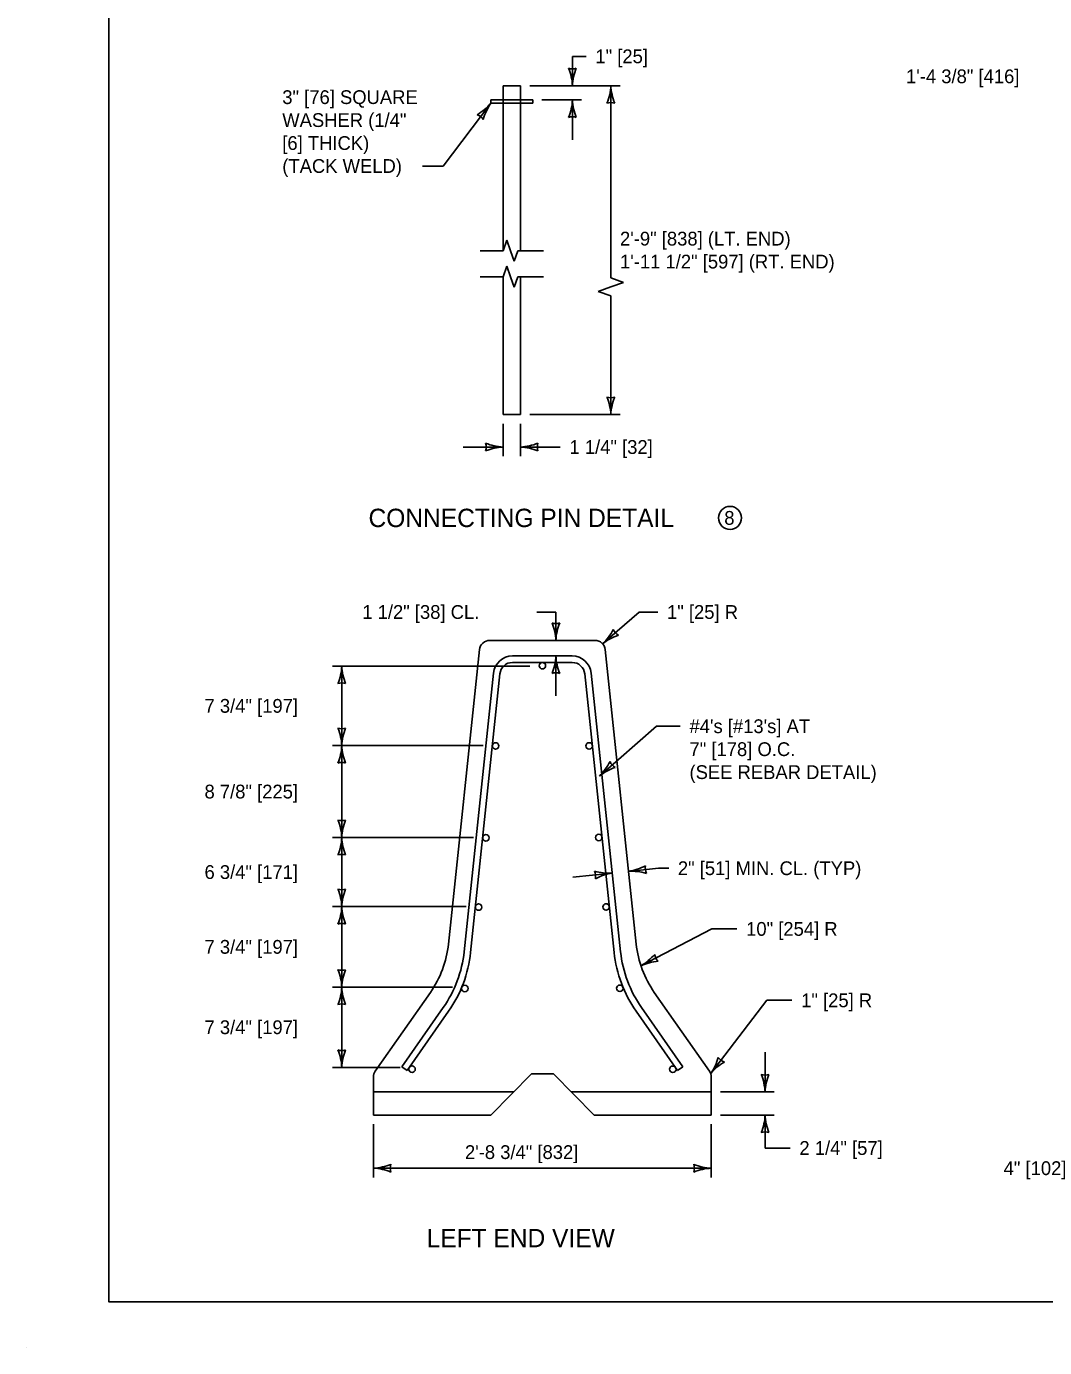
# Model space of a CAD drawing. Extents: x 49991.4 to 50021, y 49987.6 to 50011.4.
# Drawn here: x 49999.02 to 50003.46, y 49987.6 to 49993.36 of the extents above; entities that cross this region are included whole.
import ezdxf

# ---------------------------------------------------------------- set-up
doc = ezdxf.new("R2010")
doc.units = 0
for name, color, linetype in [('Level 1', 7, 'Continuous'), ('Level 2', 7, 'Continuous'), ('Level 3', 7, 'Continuous'), ('Level 4', 7, 'Continuous'), ('Level 6', 7, 'Continuous')]:
    doc.layers.add(name, color=color, linetype=linetype)

msp = doc.modelspace()

# ---------------------------------------------------------------- linework, layer by layer
at = {"layer": 'Level 1'}
for p, q in [((50001.1781, 49993.0967), (50001.1019, 49993.0967)), ((50001.1019, 49993.0967), (50001.1019, 49992.3777)), ((50001.1781, 49992.3774), (50001.1781, 49993.0967)), ((50001.0485, 49993.0358), (50001.2314, 49993.0358)), ((50001.0485, 49993.0205), (50001.0485, 49993.0358)), ((50001.2314, 49993.0205), (50001.0485, 49993.0205)), ((50001.2314, 49993.0358), (50001.2314, 49993.0205)), ((50001.1019, 49992.2643), (50001.1019, 49991.6639)), ((50001.1781, 49992.264), (50001.1781, 49991.6639)), ((50001.1019, 49991.6639), (50001.1781, 49991.6639)), ((50001.5025, 49990.6801), (50001.044, 49990.6801)), ((50000.9993, 49990.6398), (50000.864, 49989.357)), ((50001.6825, 49989.357), (50001.5472, 49990.6398)), ((50001.4033, 49990.6123), (50001.1432, 49990.6123)), ((50001.4033, 49990.5839), (50001.1432, 49990.5839)), ((50001.0604, 49990.5377), (50000.9324, 49989.3236)), ((50001.0886, 49990.5347), (50000.9606, 49989.3206)), ((50001.586, 49989.3206), (50001.458, 49990.5347)), ((50001.6142, 49989.3236), (50001.4862, 49990.5377)), ((50000.7852, 49989.1463), (50000.5452, 49988.8035)), ((50002.0013, 49988.8035), (50001.7613, 49989.1463)), ((50000.8414, 49989.0803), (50000.6604, 49988.8218)), ((50001.8861, 49988.8218), (50001.7052, 49989.0803)), ((50000.8646, 49989.0641), (50000.6837, 49988.8056)), ((50001.8629, 49988.8056), (50001.682, 49989.0641)), ((50000.5371, 49988.7778), (50000.5371, 49988.6121)), ((50000.6837, 49988.8056), (50000.6604, 49988.8218)), ((50001.2262, 49988.7921), (50001.049, 49988.6121)), ((50001.2262, 49988.7921), (50001.3218, 49988.7921)), ((50001.3218, 49988.7921), (50001.499, 49988.6121)), ((50001.8629, 49988.8056), (50001.8861, 49988.8218)), ((50002.0094, 49988.6121), (50002.0094, 49988.7778)), ((50000.5371, 49988.6121), (50001.049, 49988.6121)), ((50001.499, 49988.6121), (50002.0094, 49988.6121)), ((49999.0245, 49987.5988), (49999.0245, 49987.5988))]:
    msp.add_line(p, q, dxfattribs=at)
msp.add_lwpolyline([(49999.3835, 49998.9992), (50016.7501, 49998.9992), (50016.7501, 49987.7988), (49999.3835, 49987.7988)], close=True, dxfattribs=at)
for centre in [(50001.2733, 49990.5698), (50001.0697, 49990.2201), (50001.4769, 49990.2201), (50001.0274, 49989.8195), (50001.519, 49989.8211), (50000.9956, 49989.5181), (50001.5509, 49989.5185), (50000.935, 49989.1632), (50001.6112, 49989.1641), (50000.7052, 49988.8116), (50001.8416, 49988.8113)]:
    msp.add_circle(centre, 0.0142, dxfattribs=at)
for centre, radius, start, end in [((50001.044, 49990.6351), 0.045, 90, 173.97934), ((50001.5025, 49990.6351), 0.045, 6.02066, 90), ((50001.1432, 49990.529), 0.0833, 90, 173.97934), ((50001.1432, 49990.529), 0.0549, 90, 173.97934), ((50001.4033, 49990.529), 0.0833, 6.02066, 90), ((50001.4033, 49990.529), 0.0549, 6.02066, 90), ((50000.4169, 49989.4041), 0.4496, 325.00798, 353.97934), ((50002.1296, 49989.4041), 0.4496, 186.02066, 214.99202), ((50000.4161, 49989.378), 0.5191, 325.00798, 353.97934), ((50000.4161, 49989.378), 0.5475, 325.00798, 353.97934), ((50002.1305, 49989.378), 0.5475, 186.02066, 214.99202), ((50002.1305, 49989.378), 0.5191, 186.02066, 214.99202), ((50000.5821, 49988.7778), 0.045, 145.00798, 180), ((50001.9645, 49988.7778), 0.045, 0, 34.99202)]:
    msp.add_arc(centre, radius, start, end, dxfattribs=at)
at = {"layer": 'Level 2'}
msp.add_circle((50002.0912, 49991.2137), 0.05, dxfattribs=at)
at = {"layer": 'Level 3'}
for p, q in [((50001.4044, 49993.2247), (50001.4044, 49993.0968)), ((50001.4044, 49993.2247), (50001.4644, 49993.2247)), ((50001.2181, 49993.0968), (50001.6117, 49993.0968)), ((50001.5717, 49993.0968), (50001.5717, 49992.259)), ((50001.0485, 49993.0205), (50000.8406, 49992.7469)), ((50001.2714, 49993.0348), (50001.4443, 49993.0348)), ((50001.4043, 49993.0348), (50001.4043, 49992.8614)), ((50000.7509, 49992.7469), (50000.8406, 49992.7469)), ((50001.6263, 49992.2396), (50001.5717, 49992.259)), ((50001.6263, 49992.2396), (50001.5717, 49992.2202)), ((50001.5717, 49992.2202), (50001.5167, 49992.2007)), ((50001.5717, 49992.1813), (50001.5167, 49992.2007)), ((50001.5717, 49992.1813), (50001.5717, 49991.664)), ((50001.2181, 49991.664), (50001.6117, 49991.664)), ((50001.1018, 49991.6239), (50001.1018, 49991.4825)), ((50001.178, 49991.6239), (50001.178, 49991.4825)), ((50001.1018, 49991.5225), (50000.9284, 49991.5225)), ((50001.178, 49991.5225), (50001.3515, 49991.5225)), ((50001.2486, 49990.8036), (50001.3321, 49990.8036)), ((50001.3321, 49990.6801), (50001.3321, 49990.8036)), ((50001.5359, 49990.6653), (50001.6959, 49990.8036)), ((50001.6959, 49990.8036), (50001.7766, 49990.8036)), ((50001.2192, 49990.568), (50000.3591, 49990.568)), ((50000.3991, 49990.2215), (50000.3991, 49990.568)), ((50001.3321, 49990.6123), (50001.3321, 49990.4388)), ((50001.5219, 49990.0889), (50001.7704, 49990.306)), ((50001.7704, 49990.306), (50001.8746, 49990.306)), ((50001.0156, 49990.2215), (50000.3591, 49990.2215)), ((50000.3991, 49989.8212), (50000.3991, 49990.2215)), ((50000.9733, 49989.8212), (50000.3591, 49989.8212)), ((50000.3991, 49989.5201), (50000.3991, 49989.8212)), ((50001.4056, 49989.6479), (50001.5781, 49989.6661)), ((50001.6491, 49989.6736), (50001.7788, 49989.6873)), ((50001.7788, 49989.6873), (50001.8238, 49989.6873)), ((50000.9416, 49989.5201), (50000.3591, 49989.5201)), ((50000.3991, 49989.1693), (50000.3991, 49989.5201)), ((50001.7031, 49989.2621), (50002.0117, 49989.4229)), ((50002.0117, 49989.4229), (50002.1214, 49989.4229)), ((50000.8822, 49989.1693), (50000.3591, 49989.1693)), ((50000.3991, 49988.8196), (50000.3991, 49989.1693)), ((50002.0069, 49988.7927), (50002.2516, 49989.1118)), ((50002.2516, 49989.1118), (50002.3613, 49989.1118)), ((50002.244, 49988.7129), (50002.244, 49988.8863)), ((50000.6535, 49988.8196), (50000.3591, 49988.8196)), ((50002.0494, 49988.7129), (50002.284, 49988.7129)), ((50002.0494, 49988.6121), (50002.284, 49988.6121)), ((50002.244, 49988.4683), (50002.244, 49988.6121)), ((50000.5371, 49988.5721), (50000.5371, 49988.3404)), ((50002.0094, 49988.5721), (50002.0094, 49988.3404)), ((50002.244, 49988.4683), (50002.3537, 49988.4683)), ((50000.5371, 49988.3804), (50002.0094, 49988.3804))]:
    msp.add_line(p, q, dxfattribs=at)
for centre, radius, start, end in [((50001.4044, 49993.225), 0.0548, 252.13882, 287.86118), ((50001.1717, 49993.0853), 0.233, 2.82731, 22.07716), ((50001.6265, 49993.0877), 0.2223, 157.45601, 177.63952), ((50001.3496, 49993.106), 0.2223, 337.45601, 357.63952), ((50001.8044, 49993.1083), 0.233, 182.82731, 202.07716), ((50000.8771, 49993.1622), 0.2223, 300.23782, 320.42133), ((50001.2408, 49992.8889), 0.233, 145.60912, 164.85897), ((50001.1822, 49993.044), 0.2223, 337.45601, 357.63952), ((50001.637, 49993.0463), 0.233, 182.82731, 202.07716), ((50001.5717, 49992.9686), 0.0548, 72.13882, 107.86118), ((50000.9709, 49992.9184), 0.0548, 34.92063, 70.64299), ((50001.4043, 49992.9066), 0.0548, 72.13882, 107.86118), ((50001.5717, 49991.7922), 0.0548, 252.13882, 287.86118), ((50001.339, 49991.6525), 0.233, 2.82731, 22.07716), ((50001.7939, 49991.6549), 0.2223, 157.45601, 177.63952), ((50000.9736, 49991.5225), 0.0548, 342.13882, 17.86118), ((50001.1133, 49991.7552), 0.233, 247.92284, 267.17269), ((50001.111, 49991.3003), 0.2223, 92.36048, 112.54399), ((50001.1666, 49991.7552), 0.233, 272.82731, 292.07716), ((50001.1689, 49991.3003), 0.2223, 67.45601, 87.63952), ((50001.3063, 49991.5225), 0.0548, 162.13882, 197.86118), ((50001.3321, 49990.8083), 0.0548, 252.13882, 287.86118), ((50001.0994, 49990.6686), 0.233, 2.82731, 22.07716), ((50001.5543, 49990.6709), 0.2223, 157.45601, 177.63952), ((50001.375, 49990.8339), 0.233, 313.65876, 332.90861), ((50001.6742, 49990.4912), 0.2223, 108.28746, 128.47096), ((50001.6329, 49990.7491), 0.0548, 202.97026, 238.69263), ((50000.177, 49990.5771), 0.2223, 337.45601, 357.63952), ((50000.6318, 49990.5795), 0.233, 182.82731, 202.07716), ((50001.11, 49990.6214), 0.2223, 337.45601, 357.63952), ((50001.5648, 49990.6238), 0.233, 182.82731, 202.07716), ((50001.3321, 49990.4841), 0.0548, 72.13882, 107.86118), ((50000.3991, 49990.4398), 0.0548, 72.13882, 107.86118), ((50000.3991, 49990.3497), 0.0548, 252.13882, 287.86118), ((50000.1664, 49990.21), 0.233, 2.82731, 22.07716), ((50000.6212, 49990.2123), 0.2223, 157.45601, 177.63952), ((50000.177, 49990.2306), 0.2223, 337.45601, 357.63952), ((50000.6318, 49990.233), 0.233, 182.82731, 202.07716), ((50000.3991, 49990.0932), 0.0548, 72.13882, 107.86118), ((50001.3602, 49990.2567), 0.233, 313.95136, 333.20121), ((50001.6611, 49989.9156), 0.2223, 108.58006, 128.76356), ((50001.6185, 49990.1733), 0.0548, 203.26286, 238.98523), ((50000.3991, 49989.9494), 0.0548, 252.13882, 287.86118), ((50000.1664, 49989.8097), 0.233, 2.82731, 22.07716), ((50000.6212, 49989.812), 0.2223, 157.45601, 177.63952), ((50000.177, 49989.8303), 0.2223, 337.45601, 357.63952), ((50000.6318, 49989.8327), 0.233, 182.82731, 202.07716), ((50000.3991, 49989.693), 0.0548, 72.13882, 107.86118), ((50001.5639, 49989.888), 0.2223, 253.47668, 273.66018), ((50001.4506, 49989.6527), 0.0548, 348.15948, 23.88184), ((50001.6139, 49989.4359), 0.233, 98.84798, 118.09783), ((50001.6133, 49989.9038), 0.233, 278.84798, 298.09783), ((50001.6633, 49989.4517), 0.2223, 73.47668, 93.66018), ((50001.7767, 49989.687), 0.0548, 168.15948, 203.88184), ((50000.3991, 49989.6483), 0.0548, 252.13882, 287.86118), ((50000.1664, 49989.5086), 0.233, 2.82731, 22.07716), ((50000.6212, 49989.5109), 0.2223, 157.45601, 177.63952), ((50000.177, 49989.5292), 0.2223, 337.45601, 357.63952), ((50000.6318, 49989.5316), 0.233, 182.82731, 202.07716), ((50000.3991, 49989.3918), 0.0548, 72.13882, 107.86118), ((50001.5853, 49989.4631), 0.233, 300.35831, 319.60816), ((50001.8168, 49989.3213), 0.0548, 189.66982, 225.39218), ((50000.3991, 49989.2975), 0.0548, 252.13882, 287.86118), ((50000.1664, 49989.1578), 0.233, 2.82731, 22.07716), ((50000.6212, 49989.1601), 0.2223, 157.45601, 177.63952), ((50001.7977, 49989.0609), 0.2223, 94.98701, 115.17052), ((50000.177, 49989.1784), 0.2223, 337.45601, 357.63952), ((50000.6318, 49989.1808), 0.233, 182.82731, 202.07716), ((50000.3991, 49989.041), 0.0548, 72.13882, 107.86118), ((50000.3991, 49988.9479), 0.0548, 252.13882, 287.86118), ((50000.1664, 49988.8081), 0.233, 2.82731, 22.07716), ((50000.6212, 49988.8105), 0.2223, 157.45601, 177.63952), ((50001.8152, 49988.9252), 0.233, 325.33893, 344.58878), ((50002.1775, 49988.6502), 0.2223, 119.96763, 140.15114), ((50002.0849, 49988.8944), 0.0548, 214.65044, 250.3728), ((50002.244, 49988.8411), 0.0548, 252.13882, 287.86118), ((50002.0113, 49988.7014), 0.233, 2.82731, 22.07716), ((50002.4661, 49988.7037), 0.2223, 157.45601, 177.63952), ((50002.0219, 49988.6213), 0.2223, 337.45601, 357.63952), ((50002.4767, 49988.6236), 0.233, 182.82731, 202.07716), ((50002.244, 49988.4839), 0.0548, 72.13882, 107.86118), ((50000.5256, 49988.6131), 0.233, 272.82731, 292.07716), ((50000.528, 49988.1583), 0.2223, 67.45601, 87.63952), ((50000.6653, 49988.3804), 0.0548, 162.13882, 197.86118), ((50002.0186, 49988.6025), 0.2223, 247.45601, 267.63952), ((50001.8812, 49988.3804), 0.0548, 342.13882, 17.86118), ((50002.0209, 49988.1477), 0.233, 92.82731, 112.07716)]:
    msp.add_arc(centre, radius, start, end, dxfattribs=at)
at = {"layer": 'Level 4'}
for p, q in [((50000.5361, 49988.7129), (50001.1482, 49988.7129)), ((50002.0098, 49988.7129), (50001.3998, 49988.7129))]:
    msp.add_line(p, q, dxfattribs=at)
at = {"layer": 'Level 6'}
for p, q in [((50001.1179, 49992.4232), (50001.1018, 49992.3775)), ((50001.1341, 49992.3775), (50001.1179, 49992.4232)), ((50001.1018, 49992.3774), (50001.0019, 49992.3776)), ((50001.1018, 49992.3775), (50001.1018, 49992.3774)), ((50001.1503, 49992.3318), (50001.1341, 49992.3775)), ((50001.1665, 49992.3774), (50001.1503, 49992.3318)), ((50001.2781, 49992.3773), (50001.1665, 49992.3774)), ((50001.1179, 49992.3098), (50001.1018, 49992.2641)), ((50001.1341, 49992.2641), (50001.1179, 49992.3098)), ((50001.1018, 49992.264), (50001.0019, 49992.2642)), ((50001.1018, 49992.2641), (50001.1018, 49992.264)), ((50001.1503, 49992.2184), (50001.1341, 49992.2641)), ((50001.1665, 49992.264), (50001.1503, 49992.2184)), ((50001.2781, 49992.2639), (50001.1665, 49992.264))]:
    msp.add_line(p, q, dxfattribs=at)

# ---------------------------------------------------------------- texts
at = {"layer": 'Level 2'}
for s, height, p in [('1" [25]', 0.06, (50001.5044, 49993.1947)), ('1\'-4 3/8" [416]', 0.06, (50002.8583, 49993.1076)), ('3" [76] SQUARE', 0.06, (50000.1397, 49993.0169)), ('WASHER (1/4" ', 0.06, (50000.1397, 49992.9169)), ('[6] THICK)', 0.06, (50000.1397, 49992.8169)), ('(TACK WELD)', 0.06, (50000.1397, 49992.7169)), ('2\'-9" [838] (LT. END)', 0.06, (50001.6117, 49992.4004)), ('1\'-11 1/2" [597] (RT. END)', 0.06, (50001.6117, 49992.3004)), ('1 1/4" [32]', 0.06, (50001.3915, 49991.4925)), ('CONNECTING PIN DETAIL', 0.08, (50000.5156, 49991.1737)), ('8', 0.06, (50002.0662, 49991.1837)), ('1 1/2" [38] CL. ', 0.06, (50000.4883, 49990.7736)), ('1" [25] R', 0.06, (50001.8166, 49990.7736)), ('7 3/4" [197]', 0.06, (49999.8007, 49990.3647)), ("#4's [#13's] AT", 0.06, (50001.9146, 49990.276)), ('7" [178] O.C.', 0.06, (50001.9146, 49990.176)), ('(SEE REBAR DETAIL)', 0.06, (50001.9146, 49990.076)), ('8 7/8" [225]', 0.06, (49999.8007, 49989.9913)), ('6 3/4" [171]', 0.06, (49999.8007, 49989.6406)), ('2" [51] MIN. CL. (TYP)', 0.06, (50001.8638, 49989.6573)), ('10" [254] R', 0.06, (50002.1614, 49989.3929)), ('7 3/4" [197]', 0.06, (49999.8007, 49989.3147)), ('1" [25] R', 0.06, (50002.4013, 49989.0818)), ('7 3/4" [197]', 0.06, (49999.8007, 49988.9645)), ('2 1/4" [57]', 0.06, (50002.3937, 49988.4383)), ('2\'-8 3/4" [832]', 0.06, (50000.9359, 49988.4204)), ('4" [102]', 0.06, (50003.2837, 49988.3504)), ('LEFT END VIEW', 0.08, (50000.7687, 49988.036))]:
    msp.add_text(s, height=height, dxfattribs=at).set_placement(p)

doc.saveas('drawing.dxf')
